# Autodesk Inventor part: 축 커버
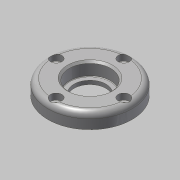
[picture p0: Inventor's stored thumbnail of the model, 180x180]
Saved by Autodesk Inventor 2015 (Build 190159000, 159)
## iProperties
Created: 2015-10
Part Number: 축 커버
Document SubType Name: Modeling
Designer: mdu
Density: 7.86 g/cm^3
Material: 강철, 연강
Mass: 76.1259 g
Surface Area: 48.0703 cm^2
Volume: 9.68523 cm^3
Appearance: 강철
Author: mdu
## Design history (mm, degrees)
sketch "스케치1"
  geometry: C1 r 22.355 at (0, 0) reference; C2 r 14 at (0, 0) reference; C3 r 1.23 at (0, 18) reference; 1 further point
extrude "돌출1" new body sketch "스케치1" distance "d0" = 8; taper "d1" = 0 deg
sketch "스케치2"
  geometry: C1 r 14 at (0, 0) reference; 1 further point
extrude "돌출2" join sketch "스케치2" distance "d2" = 3; taper "d3" = 0 deg
hole "구멍1" diameter "d6" = 17; stored, may be unused: countersink angle "d10" = 90 deg, drill point angle "d12" = 118 deg; dims "d4" = 10, "d5" = 10, "d7" = 6, "d8" = 23, "d9" = 2, "d11" = 8
hole "구멍2" diameter "d15" = 22; stored, may be unused: countersink angle "d19" = 90 deg, drill point angle "d21" = 0 deg; dims "d13" = 10, "d14" = 10, "d16" = 6, "d17" = 25, "d18" = 2, "d20" = 7
fillet "모깎기1" dims "d22" = 3, "d23" = 0.3
chamfer "모따기1" distance "d24" = 1; stored, may be unused: second distance "d25" = 2, angle "d26" = 45 deg
sketch "스케치3"
  geometry: 2 further points
hole "구멍3" sketch "스케치3" at (0, 18) diameter "d27" = 3.4; stored, may be unused: countersink angle "d31" = 90 deg, drill point angle "d33" = 118 deg; dims "d28" = 6, "d29" = 6, "d30" = 3.3, "d32" = 7
node "솔리드1"
pattern_circular "원형 패턴1" dims angle "d35" = 360 deg
node "참조1"
node "참조2"
node "참조3"
